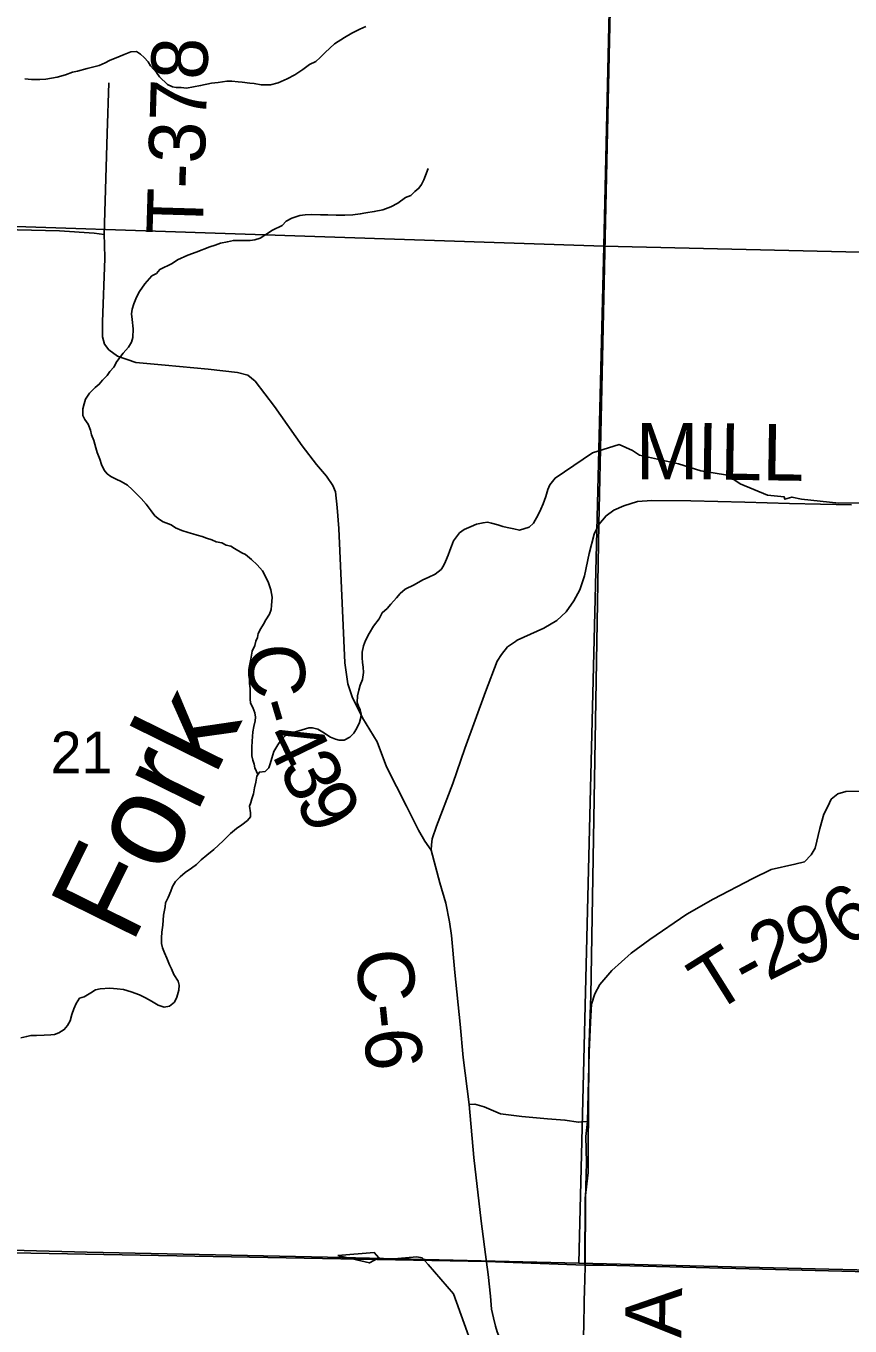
# Model space of a CAD drawing. Extents: x 0 to 34, y 0 to 22.
# Drawn here: x 6.467 to 7.298, y 16.238 to 17.548 of the extents above; entities that cross this region are included whole.
import ezdxf

# ---------------------------------------------------------------- set-up
doc = ezdxf.new("R2010")
doc.units = 0
for name, color, linetype in [('GM_X_Corporation', 7, 'Continuous'), ('GM_X_County_Road', 7, 'Continuous'), ('GM_X_County_Road_Text', 7, 'Continuous'), ('GM_X_Minor_Lake', 7, 'Continuous'), ('GM_X_Minor_River', 7, 'Continuous'), ('GM_X_Minor_River_Text', 7, 'Continuous'), ('GM_X_Section_Text', 7, 'Continuous'), ('GM_X_Township_Road', 7, 'Continuous'), ('GM_X_Township_Road_Text', 7, 'Continuous')]:
    doc.layers.add(name, color=color, linetype=linetype)

msp = doc.modelspace()

# ---------------------------------------------------------------- linework, layer by layer
at = {"layer": 'GM_X_Corporation'}
for points in [[(4.9914, 16.3477), (5.6931, 16.3352), (5.9938, 16.3204), (6.9309, 16.303), (7.0302, 16.2995), (7.0491, 16.2993), (8.0233, 16.275), (8.785, 16.2515), (8.9, 16.2485), (8.9, 20.9), (2.1, 20.9)], [(4.9914, 16.3477), (5.6931, 16.3352), (5.9938, 16.3204), (6.9309, 16.303), (7.0302, 16.2995), (7.0306, 16.367), (7.0337, 16.3927), (7.0334, 16.423), (7.0339, 16.4517), (7.0342, 16.5147), (7.0361, 16.5712), (7.0442, 17.0463), (7.0729, 18.3402), (7.0876, 19.4092), (7.1008, 19.81), (7.1249, 20.7061), (7.1302, 20.9), (2.2795, 20.9)], [(8.9, 14.5591), (8.9, 16.2485), (8.785, 16.2515), (8.0233, 16.275), (7.0491, 16.2993), (7.0302, 16.2995), (6.9309, 16.303), (5.9938, 16.3204), (5.6931, 16.3352), (4.9914, 16.3477), (4.4958, 16.358), (3.9899, 16.3631), (3.7537, 16.3728), (3.6165, 16.3686), (3.0057, 16.3809), (2.7707, 16.392), (2.3623, 16.41), (2.2605, 16.4147), (2.1155, 16.4201), (2.1, 15.9517)], [(8.9, 14.1), (8.9, 16.2485), (8.785, 16.2515), (8.0233, 16.275), (7.0491, 16.2993), (7.0302, 16.2995), (6.9309, 16.303), (5.9938, 16.3204), (5.6931, 16.3352), (4.9914, 16.3477)]]:
    msp.add_lwpolyline(points, dxfattribs=at)
for points in [[(8.9, 16.2485), (8.9, 20.9), (7.1302, 20.9), (7.1249, 20.7061), (7.1008, 19.81), (7.0876, 19.4092), (7.0729, 18.3402), (7.0442, 17.0463), (7.0361, 16.5712), (7.0342, 16.5147), (7.0339, 16.4517), (7.0334, 16.423), (7.0337, 16.3927), (7.0306, 16.367), (7.0302, 16.2995), (7.0491, 16.2993), (8.0233, 16.275), (8.785, 16.2515)], [(7.0725, 18.3472), (7.0493, 17.3262), (6.0244, 17.3604), (6.0547, 18.3798)], [(7.0725, 18.3472), (8.0825, 18.3198), (8.0536, 17.3026), (7.0493, 17.3262)], [(6.0244, 17.3604), (7.0493, 17.3262), (7.0242, 16.3016), (6.7708, 16.3075), (6.5283, 16.3127), (6.2859, 16.3188), (6.2825, 16.3189), (6.018, 16.3254), (6.0014, 16.3259)], [(8.0536, 17.3026), (8.0327, 16.2773), (7.0242, 16.3016), (7.0493, 17.3262)]]:
    msp.add_lwpolyline(points, close=True, dxfattribs=at)
at = {"layer": 'GM_X_County_Road'}
for points in [[(6.8751, 16.7176), (6.869, 16.7266), (6.8624, 16.7377), (6.8505, 16.762), (6.8302, 16.8015), (6.8208, 16.8269), (6.8061, 16.8511), (6.7955, 16.872), (6.7911, 16.8853), (6.7882, 16.9064), (6.782, 17.0418), (6.7804, 17.0631), (6.7787, 17.0788), (6.7761, 17.0851), (6.7698, 17.0945), (6.7597, 17.1064), (6.7452, 17.1251), (6.7174, 17.1646), (6.6979, 17.1902), (6.6903, 17.1963), (6.6799, 17.1991), (6.6505, 17.2024), (6.607, 17.2064), (6.5776, 17.2092), (6.5591, 17.2155), (6.5503, 17.2219), (6.546, 17.2274), (6.5439, 17.2348), (6.5439, 17.25), (6.5462, 17.314), (6.546, 17.328), (6.5455, 17.3381), (6.5356, 17.3394), (6.5006, 17.3416), (6.4153, 17.3437)], [(6.9603, 16.928), (6.9619, 16.9291), (6.9889, 16.9415), (7.0018, 16.9492), (7.0113, 16.9579), (7.0191, 16.9688), (7.0252, 16.98), (7.0297, 16.994), (7.0347, 17.0166), (7.0397, 17.036), (7.0444, 17.0457), (7.0516, 17.0547), (7.0595, 17.0601), (7.0696, 17.0646), (7.0834, 17.0689), (7.0976, 17.07), (7.1371, 17.0698), (7.1916, 17.0682), (7.2367, 17.0668), (7.2989, 17.0655)], [(6.9311, 16.3024), (6.9256, 16.3438), (6.9181, 16.408), (6.9134, 16.4613), (6.9075, 16.5088), (6.9046, 16.5422), (6.8992, 16.5945), (6.8956, 16.6317), (6.8936, 16.6454), (6.89, 16.6642), (6.8841, 16.6848), (6.8751, 16.7176), (6.8755, 16.723), (6.8764, 16.7289), (6.8807, 16.7417), (6.897, 16.7849), (6.9093, 16.8202), (6.9299, 16.8773), (6.9418, 16.9081), (6.9461, 16.9147), (6.9522, 16.9225), (6.9603, 16.928)]]:
    msp.add_lwpolyline(points, dxfattribs=at)
at = {"layer": 'GM_X_Minor_Lake'}
for points in [[(6.8224, 16.3069), (6.8179, 16.3122), (6.7811, 16.3091)], [(6.7811, 16.3091), (6.8129, 16.3017), (6.8224, 16.3069)]]:
    msp.add_lwpolyline(points, dxfattribs=at)
at = {"layer": 'GM_X_Minor_River'}
for points in [[(6.4654, 17.495), (6.4722, 17.4942), (6.4805, 17.4942), (6.4866, 17.4946), (6.498, 17.4966), (6.5067, 17.4988), (6.5135, 17.5015), (6.5188, 17.5027), (6.5283, 17.5053), (6.5404, 17.5084), (6.5464, 17.5111), (6.551, 17.5133), (6.5616, 17.5179), (6.5657, 17.5194), (6.5725, 17.5221), (6.5782, 17.5225), (6.582, 17.5199), (6.5858, 17.5165), (6.59, 17.5119), (6.5923, 17.5081), (6.5984, 17.5013), (6.6014, 17.4968), (6.6094, 17.4892), (6.6143, 17.4869), (6.6181, 17.4862), (6.6231, 17.4862), (6.6284, 17.4855), (6.6356, 17.487), (6.6428, 17.4881), (6.6537, 17.4904), (6.6606, 17.4912), (6.6693, 17.4924), (6.6742, 17.4924), (6.6806, 17.492), (6.6848, 17.4916), (6.6924, 17.4905), (6.6969, 17.4901), (6.7038, 17.489), (6.7132, 17.489), (6.7208, 17.491), (6.7299, 17.4948), (6.7378, 17.4989), (6.7458, 17.5043), (6.7526, 17.5092), (6.759, 17.5123), (6.7632, 17.5164), (6.7685, 17.5214), (6.7779, 17.5301), (6.7877, 17.5366), (6.7953, 17.5408), (6.8032, 17.545), (6.8093, 17.5476)], [(6.5812, 17.2806), (6.5865, 17.2882), (6.5937, 17.2965), (6.5982, 17.2988), (6.6016, 17.3026), (6.6141, 17.3087), (6.6194, 17.3125), (6.63, 17.3171), (6.6383, 17.3201), (6.652, 17.3255), (6.6576, 17.3274), (6.6629, 17.3293), (6.6698, 17.3308), (6.6758, 17.332), (6.6929, 17.332), (6.6974, 17.3328), (6.7027, 17.3343), (6.7152, 17.3423), (6.725, 17.3472), (6.7292, 17.3514), (6.7349, 17.3545), (6.7428, 17.3571), (6.7481, 17.3579), (6.7542, 17.3583), (6.7636, 17.3579), (6.7712, 17.358), (6.7796, 17.3576), (6.7883, 17.3576), (6.7962, 17.358), (6.8038, 17.3588), (6.8095, 17.3599), (6.8178, 17.3611), (6.8265, 17.363), (6.8345, 17.366), (6.8417, 17.3695), (6.8492, 17.3752), (6.8549, 17.3775), (6.8587, 17.3813), (6.8628, 17.3847), (6.8655, 17.3885), (6.8677, 17.393), (6.8696, 17.3976), (6.8723, 17.4044)], [(6.7005, 16.794), (6.6975, 16.8006), (6.6967, 16.8044), (6.6955, 16.8082), (6.6944, 16.8127), (6.6944, 16.8214), (6.6947, 16.8275), (6.6951, 16.8321), (6.6955, 16.837), (6.6966, 16.8423), (6.6977, 16.848), (6.6981, 16.8518), (6.6973, 16.856), (6.6954, 16.8613), (6.6931, 16.8658), (6.6927, 16.87), (6.6927, 16.8806), (6.6919, 16.8856), (6.6919, 16.8897), (6.6915, 16.8966), (6.6919, 16.9034), (6.6934, 16.9102), (6.6948, 16.9182), (6.6975, 16.9239), (6.6986, 16.9281), (6.7001, 16.9319), (6.7009, 16.936), (6.7035, 16.941), (6.7061, 16.9455), (6.7084, 16.9497), (6.7122, 16.9554), (6.714, 16.9603), (6.7144, 16.9641), (6.7148, 16.9725), (6.7136, 16.9801), (6.7113, 16.9869), (6.7086, 16.9929), (6.7052, 16.999), (6.6999, 17.0051), (6.6942, 17.0104), (6.6881, 17.0157), (6.6843, 17.0172), (6.6771, 17.0217), (6.6733, 17.024), (6.6684, 17.0251), (6.6642, 17.0274), (6.6585, 17.0285), (6.654, 17.0304), (6.6487, 17.0319), (6.6445, 17.0338), (6.6392, 17.0349), (6.635, 17.0364), (6.6301, 17.0379), (6.624, 17.0398), (6.6176, 17.0425), (6.613, 17.0455), (6.605, 17.0485), (6.6012, 17.0508), (6.5967, 17.0545), (6.5929, 17.0595), (6.5879, 17.0663), (6.583, 17.072), (6.5739, 17.0811), (6.5689, 17.0856), (6.5625, 17.089), (6.5575, 17.0916), (6.5522, 17.0943), (6.5484, 17.0969), (6.5454, 17.1007), (6.5427, 17.1064), (6.5412, 17.1117), (6.5385, 17.1182), (6.537, 17.1231), (6.5351, 17.1303), (6.5328, 17.1363), (6.5316, 17.1409), (6.5293, 17.147), (6.5259, 17.1515), (6.524, 17.1557), (6.524, 17.1625), (6.5255, 17.1674), (6.5266, 17.172), (6.5308, 17.1781), (6.5364, 17.1838), (6.5406, 17.1872), (6.544, 17.1914), (6.5485, 17.1959), (6.5512, 17.2001), (6.5553, 17.2043), (6.5583, 17.21), (6.5647, 17.2183), (6.57, 17.2244), (6.573, 17.2297), (6.5745, 17.2343), (6.5749, 17.243), (6.5737, 17.2525), (6.573, 17.2582), (6.5737, 17.2627), (6.5756, 17.268), (6.5782, 17.2749), (6.5812, 17.2806)], [(7.0378, 17.118), (7.0648, 17.1263), (7.0784, 17.1205), (7.0852, 17.1156), (7.1245, 17.1071), (7.1471, 17.0999), (7.174, 17.0956), (7.1868, 17.0869), (7.2144, 17.0754), (7.231, 17.0738), (7.2318, 17.0712), (7.239, 17.0734), (7.2488, 17.0715), (7.2862, 17.0672), (7.3282, 17.0675)], [(7.0378, 17.118), (7.0001, 17.0925), (6.9948, 17.0857), (6.993, 17.0812), (6.9907, 17.0739), (6.9881, 17.0667), (6.9858, 17.0614), (6.9832, 17.0557), (6.9783, 17.047), (6.9741, 17.0432), (6.9643, 17.0401), (6.9586, 17.0413), (6.9518, 17.0428), (6.9476, 17.0439), (6.9423, 17.0454), (6.9362, 17.0473), (6.9321, 17.048), (6.9275, 17.0476), (6.9211, 17.0461), (6.9154, 17.0438), (6.9086, 17.0408), (6.9037, 17.0373), (6.8976, 17.0294), (6.8957, 17.0241), (6.8939, 17.0195), (6.8924, 17.0149), (6.8897, 17.0085), (6.8878, 17.0043), (6.8852, 17.0005), (6.8792, 16.9956), (6.8723, 16.9925), (6.8667, 16.9902), (6.858, 16.9849), (6.8489, 16.9807), (6.844, 16.9762), (6.8402, 16.972), (6.8345, 16.9655), (6.8308, 16.9613), (6.8258, 16.9568), (6.8228, 16.9507), (6.8172, 16.9435), (6.8126, 16.9359), (6.8089, 16.929), (6.807, 16.9237), (6.8055, 16.9173), (6.8055, 16.9116), (6.8059, 16.9067), (6.8067, 16.9021), (6.8071, 16.8968), (6.806, 16.8896), (6.8037, 16.8839), (6.8022, 16.879), (6.8011, 16.8733), (6.8007, 16.8664), (6.8019, 16.8626), (6.8038, 16.8589), (6.8045, 16.8551), (6.8042, 16.8513), (6.803, 16.8463), (6.8004, 16.8406), (6.7974, 16.8357), (6.7932, 16.8315), (6.7876, 16.8285), (6.7826, 16.8285), (6.7788, 16.8296), (6.7739, 16.8315), (6.7659, 16.8364), (6.761, 16.8394), (6.7557, 16.8409), (6.7519, 16.8409), (6.7417, 16.8379), (6.7349, 16.8359), (6.7284, 16.8333), (6.7243, 16.8291), (6.7205, 16.8238), (6.7167, 16.8169), (6.7145, 16.8105), (6.713, 16.8048), (6.7115, 16.8006), (6.7077, 16.7968), (6.702, 16.7964), (6.6994, 16.7922), (6.6983, 16.7862), (6.6971, 16.7805), (6.696, 16.7744), (6.6945, 16.7695), (6.6934, 16.7657), (6.6919, 16.7619), (6.693, 16.7551), (6.6931, 16.7513), (6.69, 16.7475), (6.6844, 16.7433), (6.6791, 16.7395), (6.673, 16.7345), (6.6655, 16.7269), (6.656, 16.7182), (6.6492, 16.7125), (6.6432, 16.7079), (6.6386, 16.7033), (6.6337, 16.6995), (6.6273, 16.695)], [(6.6273, 16.695), (6.622, 16.6908), (6.6175, 16.6859), (6.6144, 16.6809), (6.6126, 16.6764), (6.6099, 16.6699), (6.6073, 16.6646), (6.6069, 16.6604), (6.6054, 16.6521), (6.6047, 16.6422), (6.6036, 16.635), (6.6032, 16.6293), (6.6032, 16.6236), (6.6044, 16.6191), (6.6063, 16.6141), (6.6086, 16.6088), (6.6113, 16.602), (6.6135, 16.5982), (6.6158, 16.5925), (6.62, 16.5857), (6.6212, 16.5815), (6.6208, 16.5766), (6.6189, 16.5694), (6.6163, 16.5644), (6.6114, 16.5603), (6.6061, 16.5595), (6.6, 16.5614), (6.5932, 16.5655), (6.5871, 16.5689), (6.581, 16.572), (6.5727, 16.575), (6.5651, 16.5772), (6.5587, 16.578), (6.5511, 16.5787), (6.5416, 16.5779), (6.5367, 16.5768), (6.5321, 16.5738), (6.5253, 16.5699), (6.5208, 16.5684), (6.5174, 16.5631), (6.5148, 16.5578), (6.5129, 16.5521), (6.5114, 16.5456), (6.5087, 16.5411), (6.5053, 16.5369), (6.4997, 16.5335), (6.4955, 16.5319), (6.4917, 16.5316), (6.4849, 16.5312), (6.4773, 16.5308), (6.4716, 16.5308), (6.4675, 16.53), (6.4614, 16.5285)], [(6.8721, 16.3002), (6.866, 16.3069), (6.8607, 16.3077), (6.8338, 16.3054), (6.83, 16.305), (6.8262, 16.3053), (6.8224, 16.3069)], [(6.8721, 16.3002), (6.8979, 16.2707), (6.927, 16.1892), (6.9589, 16.1552), (6.9643, 16.1431), (6.9652, 16.1161), (6.972, 16.1036), (6.9726, 16.0668), (6.9772, 16.0558), (6.989, 16.0415), (6.9944, 16.0164), (6.9984, 15.9558), (7.0093, 15.8947), (7.0291, 15.8709), (7.0344, 15.7726), (7.036, 15.7624), (7.0421, 15.7522)]]:
    msp.add_lwpolyline(points, dxfattribs=at)
at = {"layer": 'GM_X_Township_Road'}
for points in [[(6.5455, 17.3381), (6.5486, 17.4399), (6.5502, 17.4909)], [(7.036, 16.5443), (7.037, 16.5625), (7.0401, 16.5729), (7.0453, 16.5823), (7.0575, 16.5963), (7.0768, 16.6137), (7.0957, 16.6276), (7.133, 16.6533), (7.1596, 16.6682), (7.1997, 16.6892), (7.2182, 16.698), (7.242, 16.7035), (7.2518, 16.7059), (7.2584, 16.7129), (7.2625, 16.7198), (7.2672, 16.7395), (7.2712, 16.7539), (7.2751, 16.7615), (7.2784, 16.769), (7.2853, 16.7744), (7.2933, 16.7769), (7.3082, 16.7772)], [(7.0327, 16.4443), (7.0344, 16.5141), (7.036, 16.5443)], [(6.9134, 16.4613), (6.9193, 16.4618), (6.9287, 16.459), (6.9452, 16.452), (6.9668, 16.4491), (6.9925, 16.4468), (7.0101, 16.4457), (7.0237, 16.4434), (7.0327, 16.4443)], [(7.0305, 16.299), (7.0308, 16.3665), (7.032, 16.4029), (7.0313, 16.4292), (7.0327, 16.4443)], [(7.0045, 16.0968), (6.9987, 16.1157), (6.9934, 16.1324), (6.9873, 16.1489), (6.9824, 16.1597), (6.9784, 16.1661), (6.9745, 16.1723), (6.9648, 16.185), (6.9569, 16.197), (6.9515, 16.2086), (6.9441, 16.2264), (6.9419, 16.2322), (6.9401, 16.238), (6.938, 16.2465), (6.9362, 16.2552), (6.9349, 16.2683), (6.9328, 16.2899), (6.9311, 16.3024)], [(7.0045, 16.0968), (7.006, 16.0983), (7.0077, 16.1009), (7.0092, 16.1034), (7.0102, 16.1052), (7.0142, 16.1155), (7.0181, 16.1257), (7.0209, 16.1344), (7.023, 16.1449), (7.0244, 16.1531), (7.026, 16.1668), (7.0277, 16.1834), (7.0281, 16.1954), (7.0286, 16.2039), (7.0286, 16.2223), (7.0292, 16.2376), (7.0296, 16.2625), (7.0299, 16.2749), (7.0301, 16.2843), (7.0305, 16.299)]]:
    msp.add_lwpolyline(points, dxfattribs=at)

# ---------------------------------------------------------------- texts
at = {"layer": 'GM_X_County_Road_Text'}
for s, height, rotation, p in [('M', 0.0568, 0.1506, (7.0816, 17.0912)), ('I', 0.0568, 359.1101, (7.143, 17.0914)), ('L', 0.0568, 359.1, (7.1663, 17.091)), ('L', 0.0568, 359.0992, (7.2088, 17.0904)), ('C', 0.0568, 274.2464, (6.6892, 16.9237)), ('-', 0.0568, 286.478, (6.695, 16.8641)), ('4', 0.0568, 295.8699, (6.7053, 16.8323)), ('3', 0.0568, 296.4423, (6.7209, 16.8002)), ('9', 0.0568, 297.8832, (6.7372, 16.7675)), ('C-6', 0.05682, 275.9313, (6.7987, 16.6153))]:
    msp.add_text(s, height=height, rotation=rotation, dxfattribs=at).set_placement(p)
at = {"layer": 'GM_X_Minor_River_Text'}
msp.add_text('Fork', height=0.09468, rotation=63.7732, dxfattribs=at).set_placement((6.5731, 16.6211))
at = {"layer": 'GM_X_Section_Text'}
msp.add_text('21', height=0.04186, rotation=0, dxfattribs=at).set_placement((6.4916, 16.7952))
at = {"layer": 'GM_X_Township_Road_Text'}
for s, height, rotation, p in [('T-378', 0.05682, 88.316, (6.6448, 17.3373)), ('6', 0.0568, 34.3917, (7.2939, 16.6183)), ('9', 0.0568, 16.9076, (7.2434, 16.6)), ('2', 0.0568, 27.0561, (7.2147, 16.5851)), ('T', 0.0568, 32.1721, (7.1594, 16.552)), ('-', 0.0568, 28.4086, (7.1945, 16.5741)), ('A', 0.0568, 88.8139, (7.1273, 16.2259))]:
    msp.add_text(s, height=height, rotation=rotation, dxfattribs=at).set_placement(p)

doc.saveas('drawing.dxf')
